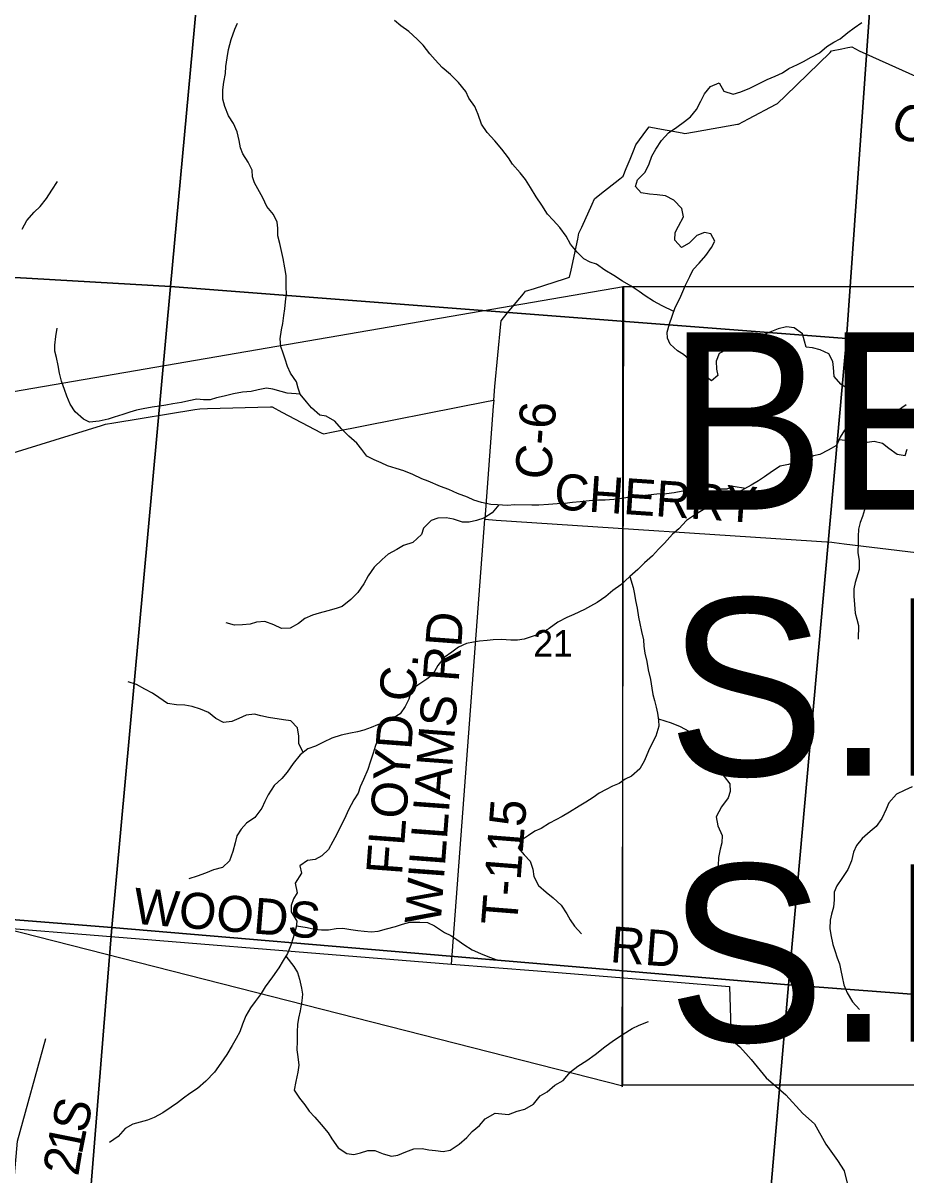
# Model space of a CAD drawing. Extents: x 0 to 42, y 0 to 22.
# Drawn here: x 5.931 to 6.628, y 14.969 to 15.878 of the extents above; entities that cross this region are included whole.
import ezdxf

# ---------------------------------------------------------------- set-up
doc = ezdxf.new("R2010")
doc.units = 0
for name, color, linetype in [('GM_X_County_Road', 7, 'Continuous'), ('GM_X_County_Road_Text', 7, 'Continuous'), ('GM_X_Major_River', 7, 'Continuous'), ('GM_X_Minor_River', 7, 'Continuous'), ('GM_X_Section', 7, 'Continuous'), ('GM_X_Section_Text', 7, 'Continuous'), ('GM_X_Township_Road', 7, 'Continuous'), ('GM_X_Township_Road_Text', 7, 'Continuous'), ('SH_Data', 7, 'Continuous')]:
    doc.layers.add(name, color=color, linetype=linetype)

msp = doc.modelspace()

# ---------------------------------------------------------------- linework, layer by layer
at = {"layer": 'GM_X_County_Road'}
for points in [[(6.40994, 15.77095), (6.41257, 15.77743), (6.41451, 15.78219), (6.41742, 15.78616), (6.42323, 15.79409), (6.42494, 15.79642), (6.43177, 15.79518), (6.45113, 15.79167), (6.45319, 15.7913), (6.46082, 15.79263), (6.49474, 15.79857), (6.49547, 15.7987), (6.50353, 15.80291), (6.52533, 15.81429), (6.52637, 15.81483), (6.53257, 15.82087), (6.56781, 15.8552), (6.56902, 15.85639), (6.57699, 15.85801), (6.58181, 15.85899), (6.58495, 15.85962), (6.59081, 15.85651), (6.71357, 15.80115)], [(5.89717, 15.53133), (5.99257, 15.56082), (5.9959, 15.56184), (6.0023, 15.56288), (6.06635, 15.57333), (6.07041, 15.57399), (6.07627, 15.57414), (6.12617, 15.57548), (6.12728, 15.5755), (6.13512, 15.57136), (6.16601, 15.55503), (6.16786, 15.55405), (6.1756, 15.5556), (6.29799, 15.57998), (6.30227, 15.58081), (6.30326, 15.59136), (6.30793, 15.64106), (6.30815, 15.64345), (6.31299, 15.64929), (6.32573, 15.66467), (6.32749, 15.66679), (6.33437, 15.66898), (6.35817, 15.67653), (6.36218, 15.6778), (6.36338, 15.68344), (6.36858, 15.70785), (6.36958, 15.71253), (6.37172, 15.71726), (6.37998, 15.73545), (6.3819, 15.73967), (6.38609, 15.74299), (6.40175, 15.75537), (6.40446, 15.75752), (6.40692, 15.76356), (6.40994, 15.77095)], [(6.30227, 15.58081), (6.30191, 15.57591), (6.29526, 15.48667), (6.30417, 15.48608), (6.56931, 15.46858), (6.57111, 15.46844), (6.57905, 15.46727), (6.71455, 15.45102)]]:
    msp.add_lwpolyline(points, dxfattribs=at)
at = {"layer": 'GM_X_Major_River'}
for points in [[(6.41871, 15.74449), (6.41419, 15.74925), (6.41573, 15.75474), (6.4218, 15.76058), (6.42504, 15.76739), (6.42715, 15.77345), (6.43019, 15.77874), (6.43476, 15.78573), (6.44027, 15.79177), (6.44671, 15.7961), (6.45278, 15.80062), (6.45771, 15.80439), (6.46227, 15.81006), (6.4657, 15.81686), (6.46875, 15.82254), (6.47349, 15.8282), (6.48012, 15.8312), (6.48406, 15.82474), (6.49142, 15.82224), (6.49748, 15.82411), (6.50448, 15.82711), (6.51073, 15.83012), (6.51812, 15.83387), (6.52437, 15.8365), (6.53023, 15.83913), (6.53535, 15.84251), (6.54217, 15.84571), (6.5469, 15.84815), (6.55296, 15.85153), (6.55941, 15.85491), (6.56529, 15.86001), (6.57078, 15.86339), (6.57589, 15.86583), (6.58177, 15.87092), (6.5867, 15.87469), (6.59296, 15.87883)], [(6.62793, 15.57694), (6.62092, 15.57223), (6.61486, 15.56885), (6.60805, 15.5685), (6.60126, 15.56929), (6.59428, 15.57254), (6.58995, 15.57749), (6.58658, 15.58414), (6.58131, 15.59004), (6.57623, 15.59328), (6.57096, 15.59937), (6.57061, 15.60639), (6.56988, 15.61132), (6.56669, 15.6174), (6.56009, 15.62046), (6.55386, 15.62201), (6.54895, 15.62241), (6.54765, 15.62715), (6.54597, 15.63303), (6.53957, 15.6378), (6.53333, 15.63859), (6.52671, 15.6371), (6.51895, 15.63392), (6.51233, 15.63091), (6.5057, 15.62829), (6.49945, 15.62585), (6.49302, 15.62304), (6.48639, 15.62061), (6.48014, 15.6176), (6.47785, 15.61155), (6.4782, 15.60529), (6.47912, 15.60017), (6.47419, 15.59602), (6.46779, 15.60079), (6.46346, 15.60574), (6.45801, 15.61164), (6.45217, 15.61678), (6.44727, 15.61965), (6.44162, 15.62479), (6.43956, 15.62954), (6.43921, 15.63428), (6.44112, 15.64109), (6.44323, 15.64696), (6.44553, 15.65377), (6.44915, 15.66096), (6.45144, 15.66644), (6.45373, 15.67155), (6.45716, 15.67836), (6.45983, 15.68384), (6.46439, 15.68894), (6.46971, 15.69498), (6.47408, 15.70121), (6.47675, 15.70613), (6.47375, 15.71202), (6.46865, 15.71299), (6.46259, 15.71074), (6.45652, 15.70452), (6.45064, 15.70113), (6.44538, 15.70703), (6.44559, 15.71309), (6.44826, 15.71801), (6.45207, 15.72538), (6.45078, 15.73202), (6.44438, 15.7385), (6.43778, 15.74213), (6.43136, 15.74273), (6.42532, 15.74332), (6.41871, 15.74449)]]:
    msp.add_lwpolyline(points, dxfattribs=at)
at = {"layer": 'GM_X_Minor_River'}
for points in [[(6.09186, 15.85096), (6.09303, 15.85759), (6.09514, 15.86554), (6.09801, 15.87349), (6.10011, 15.87841)], [(6.44448, 15.65065), (6.43514, 15.65514), (6.42835, 15.65878), (6.42194, 15.66298), (6.41705, 15.6666), (6.41083, 15.6708), (6.40404, 15.67462), (6.39707, 15.6792), (6.38991, 15.6834), (6.38331, 15.68798), (6.37841, 15.68971), (6.37351, 15.69238), (6.36824, 15.69752), (6.36297, 15.7038), (6.35941, 15.71026), (6.35452, 15.71692), (6.34926, 15.72282), (6.34474, 15.72758), (6.34024, 15.73461), (6.33592, 15.74126), (6.33123, 15.74849), (6.32729, 15.75495), (6.32315, 15.76027), (6.31714, 15.76712), (6.31394, 15.77207), (6.30868, 15.77872), (6.30323, 15.78538), (6.29721, 15.79204), (6.29271, 15.79851), (6.2899, 15.8061), (6.28748, 15.81255), (6.28259, 15.81921), (6.28016, 15.82434), (6.27452, 15.83157), (6.26812, 15.83766), (6.26153, 15.84337), (6.25607, 15.84928), (6.25175, 15.85422), (6.24649, 15.86088), (6.24197, 15.86564), (6.23539, 15.87173), (6.22898, 15.87612), (6.22408, 15.88031)], [(6.50108, 15.51109), (6.4914, 15.51255), (6.48629, 15.51049), (6.48119, 15.51051), (6.47458, 15.51206), (6.46929, 15.51189), (6.46343, 15.5104), (6.45794, 15.50948), (6.45151, 15.50875), (6.4447, 15.50745), (6.43865, 15.50672), (6.43109, 15.50657), (6.42429, 15.50584), (6.4188, 15.5053), (6.41181, 15.50438), (6.40311, 15.50309), (6.39706, 15.50217), (6.39025, 15.50164), (6.38496, 15.50185), (6.37759, 15.50112), (6.3706, 15.5004), (6.36455, 15.49986), (6.35831, 15.49913), (6.35226, 15.49878), (6.34545, 15.49824), (6.33789, 15.4977), (6.33241, 15.49792), (6.3188, 15.49798), (6.31313, 15.49744), (6.3052, 15.49804), (6.3001, 15.49825), (6.29273, 15.49999), (6.28669, 15.50173), (6.2816, 15.50402), (6.27368, 15.5069), (6.26689, 15.51016), (6.26029, 15.51265), (6.25048, 15.51686), (6.24557, 15.51859), (6.23841, 15.52204), (6.23143, 15.52491), (6.22539, 15.52664), (6.2184, 15.52895), (6.21331, 15.53125), (6.20784, 15.53355), (6.20218, 15.53641), (6.19805, 15.54174), (6.1941, 15.54688), (6.18789, 15.5524), (6.18206, 15.55811), (6.17679, 15.56401), (6.17001, 15.56802), (6.16491, 15.5688), (6.15851, 15.57452), (6.15437, 15.57928), (6.14948, 15.58555), (6.14799, 15.5903), (6.14669, 15.59523), (6.14181, 15.60189), (6.13956, 15.60739), (6.1377, 15.61309), (6.13602, 15.61783), (6.13434, 15.62315), (6.13361, 15.62903), (6.13477, 15.63622), (6.13574, 15.64115), (6.13652, 15.64759), (6.13749, 15.65289), (6.13789, 15.65839), (6.13868, 15.66483), (6.13851, 15.66975), (6.13853, 15.67449), (6.13836, 15.67923), (6.13744, 15.68511), (6.13596, 15.69251), (6.13448, 15.69972), (6.13337, 15.70446), (6.13188, 15.71034), (6.13191, 15.71641), (6.13136, 15.72115), (6.12837, 15.72723), (6.12329, 15.73369), (6.11992, 15.74053), (6.11617, 15.74756), (6.11336, 15.75231), (6.11187, 15.75706), (6.1117, 15.76218), (6.10851, 15.76863), (6.1042, 15.7751), (6.10233, 15.77984), (6.10122, 15.78572), (6.09974, 15.79255), (6.09674, 15.7992), (6.09299, 15.80528), (6.09, 15.8125), (6.08851, 15.81819), (6.08854, 15.82577), (6.08932, 15.83164), (6.09049, 15.83865), (6.09089, 15.84414), (6.09186, 15.85096)], [(5.93008, 15.71561), (5.9337, 15.72261), (5.9394, 15.72922), (5.94414, 15.73355), (5.94927, 15.73978), (5.95346, 15.74659), (5.95784, 15.75339)], [(6.14968, 15.58531), (6.13928, 15.58636), (6.13437, 15.58752), (6.12796, 15.58944), (6.12286, 15.59022), (6.11624, 15.58874), (6.11075, 15.58762), (6.10395, 15.58709), (6.09695, 15.5856), (6.08938, 15.58374), (6.08333, 15.58244), (6.07841, 15.58095), (6.07331, 15.58097), (6.06802, 15.58137), (6.06159, 15.58026), (6.05572, 15.57896), (6.0491, 15.57786), (6.04343, 15.57674), (6.03851, 15.57601), (6.03265, 15.57509), (6.02566, 15.57398), (6.02017, 15.57268), (6.01506, 15.57119), (6.00957, 15.56932), (6.00276, 15.56726), (5.99784, 15.56577), (5.99084, 15.56409), (5.98328, 15.56337), (5.97838, 15.56567), (5.97198, 15.57138), (5.96803, 15.57746), (5.96523, 15.58373), (5.96355, 15.58924), (5.96112, 15.59569), (5.95964, 15.60214), (5.95853, 15.60802), (5.95704, 15.61428), (5.95593, 15.6194), (5.95595, 15.62414), (5.95674, 15.63096), (5.95771, 15.63759)], [(6.59656, 15.57148), (6.59159, 15.56403), (6.58534, 15.56045), (6.57909, 15.55707), (6.57567, 15.5514), (6.5728, 15.54497), (6.56617, 15.54121), (6.55973, 15.53783), (6.55463, 15.53671), (6.548, 15.5339), (6.54213, 15.53203), (6.53494, 15.52998), (6.52851, 15.52849), (6.52226, 15.52473), (6.516, 15.52021), (6.51127, 15.51701), (6.50539, 15.51362), (6.50028, 15.51061), (6.49441, 15.50742), (6.48721, 15.50423), (6.4802, 15.50009), (6.47376, 15.4969), (6.46751, 15.49408), (6.46145, 15.49032), (6.45444, 15.48561), (6.44836, 15.4792), (6.44343, 15.47505), (6.43697, 15.46788), (6.43242, 15.46297), (6.42767, 15.45787), (6.42141, 15.4524), (6.4161, 15.44712), (6.40965, 15.44146), (6.40263, 15.43505), (6.39618, 15.43053), (6.39068, 15.42563), (6.38405, 15.42111), (6.37874, 15.4181), (6.37401, 15.41547), (6.36549, 15.41153), (6.36, 15.40909), (6.3528, 15.40533), (6.34597, 15.40043), (6.33915, 15.39649), (6.33348, 15.39443), (6.32628, 15.39199), (6.32118, 15.39126), (6.3157, 15.39129), (6.30833, 15.39189), (6.3019, 15.39154), (6.29699, 15.39099), (6.29113, 15.39045), (6.28621, 15.38971), (6.28091, 15.3886), (6.27448, 15.3856), (6.26917, 15.38183), (6.26329, 15.3775), (6.25816, 15.37127), (6.25416, 15.36408), (6.24942, 15.3605), (6.24241, 15.3558), (6.23748, 15.35222), (6.23518, 15.34465), (6.23251, 15.33897), (6.22852, 15.33311), (6.22226, 15.32935), (6.21715, 15.32653), (6.21053, 15.32429), (6.20542, 15.32241), (6.19974, 15.32017), (6.19463, 15.31886), (6.18914, 15.31794), (6.18196, 15.31627), (6.17457, 15.31384), (6.16795, 15.31064), (6.16151, 15.30745), (6.15545, 15.30539), (6.14939, 15.30068), (6.14406, 15.29388), (6.13931, 15.28708), (6.13513, 15.28198), (6.12906, 15.27651), (6.1243, 15.26914), (6.12163, 15.26385), (6.11916, 15.25855), (6.11383, 15.25138), (6.1072, 15.24686), (6.10283, 15.24195), (6.09941, 15.23685), (6.09806, 15.23136), (6.09633, 15.22435), (6.09384, 15.21716), (6.08815, 15.21169), (6.08096, 15.21002), (6.07471, 15.20739), (6.06828, 15.20496), (6.06165, 15.20271)], [(6.57491, 15.5497), (6.58208, 15.54891), (6.5885, 15.54679), (6.5953, 15.54733), (6.60249, 15.54824), (6.60909, 15.5467), (6.61418, 15.5427), (6.62077, 15.53812), (6.62701, 15.53714), (6.62873, 15.54206)], [(6.59092, 15.54698), (6.59223, 15.53616), (6.59409, 15.52895), (6.59501, 15.52421), (6.59518, 15.51909), (6.59572, 15.5134), (6.59626, 15.50752), (6.59642, 15.5007), (6.59488, 15.49407), (6.59335, 15.48896), (6.59163, 15.48404), (6.59028, 15.47874), (6.59007, 15.47306), (6.58986, 15.46813), (6.58982, 15.46055), (6.59074, 15.45391), (6.59071, 15.4469), (6.58764, 15.43668), (6.58668, 15.43175), (6.58665, 15.42607), (6.58719, 15.41943), (6.58773, 15.4126), (6.58884, 15.40786), (6.59014, 15.40293), (6.5901, 15.39212)], [(6.30645, 15.49795), (6.30101, 15.49181), (6.29457, 15.48766), (6.2887, 15.48561), (6.28284, 15.48431), (6.27774, 15.48433), (6.27057, 15.48664), (6.26471, 15.4878), (6.2581, 15.48764), (6.2528, 15.48558), (6.24691, 15.47954), (6.24538, 15.47462), (6.23855, 15.4684), (6.23117, 15.46597), (6.22568, 15.46277), (6.21905, 15.4592), (6.21412, 15.45505), (6.20785, 15.44882), (6.20329, 15.44202), (6.19986, 15.43559), (6.19492, 15.42898), (6.1896, 15.42332), (6.18277, 15.41785), (6.17785, 15.41617), (6.17142, 15.41449), (6.16461, 15.41244), (6.15931, 15.41095), (6.15325, 15.40832), (6.14813, 15.40436), (6.14169, 15.40079), (6.13489, 15.40044), (6.12866, 15.40332), (6.12168, 15.406), (6.11507, 15.40546), (6.11015, 15.40397), (6.1041, 15.40324), (6.09767, 15.40308), (6.09106, 15.40481)], [(6.40961, 15.44144), (6.41244, 15.43292), (6.41337, 15.42761), (6.4141, 15.42268), (6.41559, 15.41642), (6.41669, 15.4094), (6.41761, 15.40447), (6.41891, 15.39821), (6.42039, 15.39138), (6.42075, 15.38645), (6.42167, 15.38095), (6.42315, 15.37431), (6.42426, 15.36786), (6.42611, 15.36027), (6.42722, 15.35325), (6.42776, 15.34832), (6.42907, 15.34358), (6.43056, 15.33845), (6.43167, 15.33352), (6.4324, 15.32821), (6.43257, 15.32328), (6.43027, 15.31552), (6.4276, 15.31041), (6.42436, 15.30379), (6.4213, 15.29623), (6.41768, 15.2898), (6.41104, 15.28395), (6.40612, 15.28151), (6.40119, 15.27812), (6.39608, 15.27587), (6.39116, 15.27324), (6.38547, 15.27042), (6.38073, 15.26703), (6.37505, 15.26327), (6.36974, 15.26026), (6.36216, 15.25537), (6.35629, 15.25198), (6.35137, 15.24954), (6.34625, 15.24691), (6.33962, 15.24258), (6.3347, 15.24052), (6.32977, 15.23713), (6.32503, 15.23393), (6.3216, 15.22731), (6.3263, 15.22179), (6.33101, 15.21684), (6.33306, 15.21039), (6.33398, 15.2047), (6.33754, 15.19748), (6.34375, 15.19233), (6.34921, 15.18795), (6.35542, 15.18205), (6.36012, 15.1752), (6.36274, 15.17045), (6.36612, 15.16551), (6.37158, 15.15942)], [(6.15174, 15.30251), (6.14848, 15.30978), (6.14832, 15.31547), (6.1474, 15.32211), (6.14213, 15.32744), (6.13628, 15.32841), (6.12438, 15.33017), (6.11834, 15.33153), (6.11343, 15.33288), (6.10681, 15.33196), (6.10113, 15.32933), (6.09564, 15.32708), (6.08902, 15.32635), (6.08299, 15.32941), (6.07715, 15.33418), (6.07074, 15.33686), (6.06432, 15.33879), (6.05847, 15.33995), (6.05186, 15.34017), (6.04487, 15.34134), (6.0379, 15.34592), (6.033, 15.34935), (6.02678, 15.3526), (6.02018, 15.35623), (6.01376, 15.35835)], [(6.2134, 15.32526), (6.21239, 15.31821), (6.21066, 15.31235), (6.20875, 15.30743), (6.20703, 15.30194), (6.20473, 15.29494), (6.20281, 15.28907), (6.19957, 15.28131), (6.1969, 15.27545), (6.19517, 15.27034), (6.19194, 15.26524), (6.18756, 15.2573), (6.1845, 15.25011), (6.18127, 15.24406), (6.17841, 15.238), (6.17536, 15.23233), (6.17174, 15.22609), (6.16661, 15.221), (6.16131, 15.21818), (6.15526, 15.21726), (6.14919, 15.21312), (6.15049, 15.20724), (6.14555, 15.19949), (6.14721, 15.1919), (6.14417, 15.18699), (6.14244, 15.18169), (6.14242, 15.17676), (6.14693, 15.16935), (6.14634, 15.16461), (6.14385, 15.15628), (6.14212, 15.1506), (6.13945, 15.14379), (6.13602, 15.13831), (6.13278, 15.13245), (6.12765, 15.12546), (6.12176, 15.11753), (6.11871, 15.11223), (6.11396, 15.106), (6.11035, 15.1009), (6.10654, 15.09466), (6.10406, 15.08823), (6.10176, 15.08217), (6.0989, 15.07669), (6.09586, 15.07121), (6.09167, 15.06421), (6.08691, 15.05722), (6.08178, 15.05023), (6.07514, 15.04306), (6.0685, 15.03741), (6.06243, 15.03345), (6.0575, 15.02968), (6.05276, 15.02591), (6.04765, 15.02272), (6.04101, 15.0182), (6.03419, 15.01444), (6.02889, 15.01238), (6.02322, 15.0107), (6.01735, 15.00921), (6.01129, 15.00582), (6.00578, 14.9994), (5.99896, 14.9947)], [(6.43228, 15.32911), (6.44241, 15.32608), (6.44939, 15.3232), (6.45636, 15.31938), (6.46219, 15.31329), (6.46557, 15.30797), (6.46933, 15.30226), (6.47365, 15.29561), (6.47797, 15.29066), (6.48418, 15.28362), (6.48869, 15.27773), (6.48904, 15.27166), (6.48732, 15.26674), (6.482, 15.25975), (6.4778, 15.25181), (6.47909, 15.2446), (6.48265, 15.237), (6.48244, 15.23132), (6.48109, 15.22621), (6.47974, 15.21958), (6.47934, 15.21333), (6.47761, 15.20822), (6.47249, 15.20217)], [(6.63268, 15.27537), (6.62681, 15.27274), (6.62018, 15.26955), (6.6141, 15.26294), (6.612, 15.25783), (6.60857, 15.25046), (6.60419, 15.24422), (6.59945, 15.24026), (6.59319, 15.2346), (6.58863, 15.22913), (6.58616, 15.22383), (6.58461, 15.21702), (6.58194, 15.21021), (6.57718, 15.20303), (6.57319, 15.19736), (6.57109, 15.19244), (6.57106, 15.18637), (6.57047, 15.1805), (6.56894, 15.17501), (6.56797, 15.17009), (6.56756, 15.16364), (6.5683, 15.15852), (6.56997, 15.15112), (6.57165, 15.14638), (6.57351, 15.14049), (6.57519, 15.13575), (6.5763, 15.13044), (6.57723, 15.1255), (6.57871, 15.11905), (6.58133, 15.11279), (6.58545, 15.10576), (6.5911, 15.09966)], [(6.14649, 15.16584), (6.15503, 15.16438), (6.16088, 15.16322), (6.16636, 15.16262), (6.17184, 15.1626), (6.17789, 15.16371), (6.18319, 15.16387), (6.18961, 15.1629), (6.19489, 15.16193), (6.2, 15.16152), (6.20566, 15.16112), (6.21114, 15.16147), (6.21758, 15.16334), (6.22477, 15.1652), (6.23025, 15.16707), (6.23612, 15.16875), (6.24406, 15.16871), (6.2501, 15.16831), (6.25557, 15.16582), (6.2633, 15.16048), (6.26839, 15.15818), (6.27329, 15.15494), (6.27875, 15.15112), (6.28535, 15.14692), (6.29176, 15.14386), (6.29761, 15.14156), (6.30384, 15.13907)], [(6.13819, 15.14179), (6.1445, 15.13372), (6.14751, 15.12878), (6.149, 15.12366), (6.15067, 15.11645), (6.15121, 15.11171), (6.15081, 15.1064), (6.14946, 15.09864), (6.1483, 15.09296), (6.14733, 15.08784), (6.14712, 15.08197), (6.14708, 15.07477), (6.14687, 15.06794), (6.1476, 15.06244), (6.14851, 15.05562), (6.14773, 15.05012), (6.146, 15.04293), (6.14484, 15.03592), (6.14897, 15.02965), (6.1531, 15.02451), (6.15667, 15.01938), (6.16119, 15.01462), (6.16607, 15.00891), (6.17153, 15.00244), (6.17453, 14.9975), (6.17941, 14.99047), (6.18639, 14.98607), (6.19186, 14.9851), (6.19716, 14.98659), (6.20303, 14.98846), (6.20832, 14.98844), (6.21511, 14.98575), (6.22153, 14.98402), (6.22663, 14.98457), (6.23288, 14.98738), (6.23931, 14.98962), (6.24593, 14.98997), (6.25103, 14.98881), (6.25632, 14.98841), (6.26236, 14.98762), (6.26785, 14.98874), (6.27505, 14.99344), (6.28112, 14.99853), (6.2853, 15.00344), (6.29099, 15.00815), (6.29554, 15.01344), (6.3035, 15.01795), (6.3086, 15.01736), (6.31408, 15.01677), (6.32089, 15.01939), (6.32676, 15.02107), (6.33358, 15.02502), (6.3389, 15.03144), (6.34458, 15.03464), (6.35046, 15.03992), (6.35709, 15.04368), (6.36279, 15.05047), (6.36867, 15.055), (6.37568, 15.05932), (6.38231, 15.06422), (6.39009, 15.07025), (6.39691, 15.07534), (6.40449, 15.08023), (6.41169, 15.08456), (6.417, 15.08738), (6.42438, 15.09019)]]:
    msp.add_lwpolyline(points, dxfattribs=at)
at = {"layer": 'GM_X_Section'}
for points in [[(5.55229, 16.21494), (6.09307, 16.16969), (6.04727, 15.6704), (5.50081, 15.70202)], [(6.09307, 16.16969), (6.61604, 16.129), (6.58067, 15.62951), (6.04727, 15.6704)], [(6.61604, 16.129), (7.14959, 16.08663), (7.1079, 15.58159), (6.58067, 15.62951)], [(6.04727, 15.6704), (6.00071, 15.16448), (5.46922, 15.20689), (5.50081, 15.70202)], [(6.04727, 15.6704), (6.58067, 15.62951), (6.53505, 15.11904), (6.00071, 15.16448)], [(6.58067, 15.62951), (7.1079, 15.58159), (7.06657, 15.07902), (6.53505, 15.11904)], [(5.46922, 15.20689), (6.00071, 15.16448), (5.95983, 14.65439), (5.42587, 14.69605)], [(6.00071, 15.16448), (6.53505, 15.11904), (6.49171, 14.62012), (5.95983, 14.65439)], [(6.53505, 15.11904), (7.06657, 15.07902), (7.02582, 14.56792), (6.49171, 14.62012)]]:
    msp.add_lwpolyline(points, close=True, dxfattribs=at)
at = {"layer": 'GM_X_Township_Road'}
msp.add_line((6.2689, 15.1356), (6.29526, 15.48667), dxfattribs=at)
for points in [[(5.59854, 15.18971), (5.86708, 15.16804), (5.8697, 15.16783), (6.03236, 15.1547), (6.03885, 15.15417)], [(6.03885, 15.15417), (6.15519, 15.14478), (6.2689, 15.1356), (6.33695, 15.1301)], [(6.33695, 15.1301), (6.44383, 15.12147), (6.48845, 15.11787), (6.48959, 15.07611), (6.49655, 15.07026), (6.50341, 15.06271)], [(5.91848, 14.9055), (5.9263, 14.99567), (5.94869, 15.0767)], [(6.50341, 15.06271), (6.5056, 15.06029), (6.51738, 15.0458), (6.53278, 15.03221), (6.54636, 15.01771), (6.55542, 15.00956), (6.56448, 14.99325), (6.57354, 14.98057), (6.57897, 14.97242), (6.5835, 14.9543)]]:
    msp.add_lwpolyline(points, dxfattribs=at)
at = {"layer": 'SH_Data'}
for points in [[(6.40421, 15.03928), (4.92613, 15.41609), (6.40469, 15.67044), (6.40349, 15.039)], [(6.40426, 15.67051), (7.86242, 15.67051), (7.86242, 15.04008), (6.40426, 15.04008)]]:
    msp.add_lwpolyline(points, close=True, dxfattribs=at)

# ---------------------------------------------------------------- texts
at = {"layer": 'GM_X_County_Road_Text'}
for s, rotation, p in [('C-5', 335.89873, (6.6134, 15.79218)), ('C-6', 85.88232, (6.34737, 15.51744)), ('CHERRY', 356.09588, (6.34931, 15.49464))]:
    msp.add_text(s, height=0.028409, rotation=rotation, dxfattribs=at).set_placement(p)
at = {"layer": 'GM_X_Section_Text'}
msp.add_text('21', height=0.020928, rotation=0.00001, dxfattribs=at).set_placement((6.33355, 15.37825))
at = {"layer": 'GM_X_Township_Road_Text'}
for s, height, rotation, p in [('WILLIAMS RD', 0.0284091, 85.7444, (6.26031, 15.16626)), ('FLOYD C.', 0.028409, 85.71848, (6.22987, 15.20538)), ('T-115', 0.028409, 85.49271, (6.32062, 15.16544)), ('WOODS', 0.028409, 355.31424, (6.01713, 15.16753)), ('RD', 0.028409, 355.56412, (6.39358, 15.13712)), ('S', 0.02841, 76.52447, (5.9804, 15.00114)), ('1', 0.02841, 78.59192, (5.97703, 14.98439)), ('2', 0.02841, 80.61657, (5.97425, 14.96752))]:
    msp.add_text(s, height=height, rotation=rotation, dxfattribs=at).set_placement(p)
at = {"layer": 'SH_Data'}
for s, p in [('BEGIN PROJECT', (6.43921, 15.49428)), ('S.R. 93                ', (6.43921, 15.28428)), ('S.L.M. 4.67        ', (6.43921, 15.07428))]:
    msp.add_text(s, height=0.1399997, dxfattribs=at).set_placement(p)

doc.saveas('drawing.dxf')
